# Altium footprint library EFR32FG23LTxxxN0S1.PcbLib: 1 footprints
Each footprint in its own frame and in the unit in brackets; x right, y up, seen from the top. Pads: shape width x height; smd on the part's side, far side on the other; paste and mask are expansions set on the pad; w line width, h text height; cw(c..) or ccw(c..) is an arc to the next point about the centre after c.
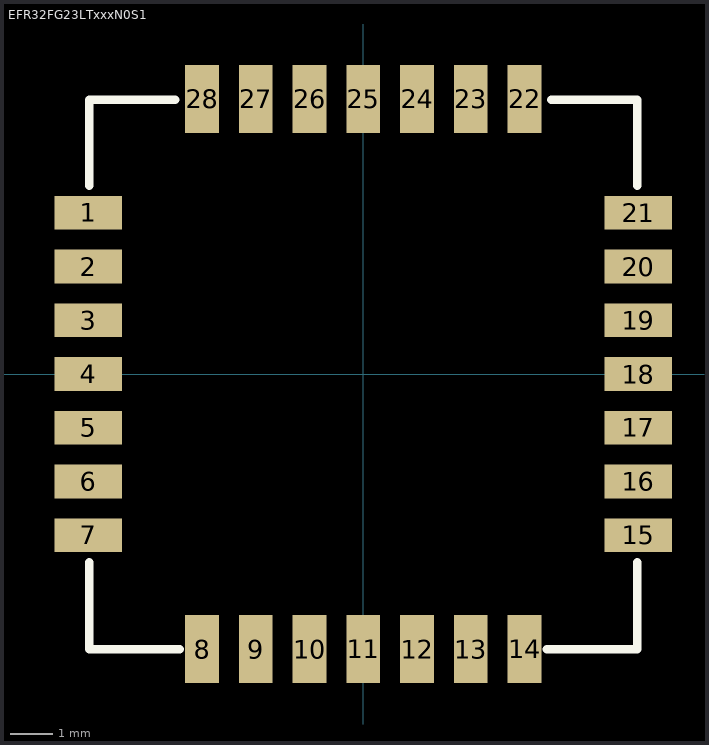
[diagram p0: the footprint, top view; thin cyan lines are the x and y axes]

## EFR32FG23LTxxxN0S1 [mm]
pads (29):
  round 1 on Top Overlay: 1(-7.239,5.842)
  rect 1.6x0.8 smd paste+0: 1(-6.5,3.81) 2(-6.5,2.54) 3(-6.5,1.27) 4(-6.5,0) 5(-6.5,-1.27) 6(-6.5,-2.54) 7(-6.5,-3.81) 15(6.5,-3.81) 16(6.5,-2.54) 17(6.5,-1.27) 18(6.5,0) 19(6.5,1.27) 20(6.5,2.54) 21(6.5,3.81)
  rect 0.8x1.6 smd paste+0: 8(-3.81,-6.5) 9(-2.54,-6.5) 10(-1.27,-6.5) 11(0,-6.5) 12(1.27,-6.5) 13(2.54,-6.5) 14(3.81,-6.5) 22(3.81,6.5) 23(2.54,6.5) 24(1.27,6.5) 25(0,6.5) 26(-1.27,6.5) 27(-2.54,6.5) 28(-3.81,6.5)
Top Overlay:
  lines w0.2: -6.477,-4.445 -6.477,-6.5 -4.341,-6.5 ; -6.477,4.445 -6.477,6.477 -4.445,6.477 ; 4.341,-6.5 6.477,-6.5 6.477,-4.445 ; 4.445,6.477 6.477,6.477 6.477,4.445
